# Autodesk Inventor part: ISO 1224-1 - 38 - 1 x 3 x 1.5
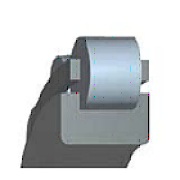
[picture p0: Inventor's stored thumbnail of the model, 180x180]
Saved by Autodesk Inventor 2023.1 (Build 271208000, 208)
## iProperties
IsCustomPart: 0
Created: 2020-01
Part Number: ISO 1224-1 - 38 - 1 x 3 x 1.5
Material: Steel, Mild
Description: Rolling bearings - Instrument precision bearings
Document SubType Name: Modeling
Standard: ISO 1224-1
Designer: ftrauzettel
Standard Revision: First edition 2007-06-15
Standards Organization: ISO
Language: en-US
Size Designation: 38 - 1 x 3 x 1.5
Categories: <MemberInstance><Categories><Category DisplayName="Shaft Parts" InternalName="7f7aeb1f-a693-4053-b835-cee3144e0d98" Mnemonic="SHFT"><Category DisplayName="Beari
Density: 7.85 g/cm^3
Appearance: Semi-Polished
Author: ftrauzettel
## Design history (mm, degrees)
sketch "Sketch"
  geometry: L1 (0, 0)-(1.5, 0); L2 (0, 0)-(0, 0.5); L3 (0, 0.5)-(1.5, 0.5); L4 (1.5, 0.5)-(1.5, 1.5); L5 (1.5, 1.5)-(0, 1.5); L6 (0, 1.5)-(0, 0.5); L7 (0, 1)-(1.5, 1); L8 (0, 1.167)-(1.5, 1.167); L9 (0, 0.833)-(1.5, 0.833)
  constraints: 18 end point, 4 point on line, 3 parallel, 3 perpendicular, 2 horizontal, 2 midpoint, 1 other
  dimensions: "d0" = 1.5 distance of L2.end L3.end (= KB); "d1" = 1 diameter of L3 L1 (= WD); "d2" = 1.66667 diameter of L9 L1 (= 0.333333 x BD + 0.666667 x WD); "d3" = 3 diameter of L5 L1 (= BD)
revolve "Body" sketch "Sketch" stored, may be unused: angle "d4" = 90 deg
body "Solid1"
fillet "Fillet1" dims "d5" = 0.05 (= KRS)
other parameters: "WD" = 1 [user parameter; used in 3 equation terms], "BD" = 3 [user parameter; used in 3 equation terms], "KB" = 1.5 [user parameter; used in 1 equation term], "d6" = 0, "d7" = 0, "d8" = 0, "d9" = 0, "d10" = 0, "KRS" = 0.05 [user parameter; used in 1 equation term], "BC0" = 41000 [user parameter], "BBA" = 0 [user parameter], "BC" = 100000 [user parameter], "KR1S" = 0.05 [user parameter], "BR" = 1.5 (= 0.5 x BD) [user parameter], "WR" = 0.5 (= 0.5 x WD) [user parameter]
